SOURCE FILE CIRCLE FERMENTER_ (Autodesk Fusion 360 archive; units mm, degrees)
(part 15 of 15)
sketch "Schizzo13" plane through (0, 25.4136, 0) normal (0, 1, 0) x axis (-1, 0, 0)
  line L1 (6.7534, 68.1854) -> (79.5534, 68.1854)
  line L2 (0.7534, -16.6146) -> (0.7534, 62.1854)
  line L3 (79.5534, -22.6146) -> (6.7534, -22.6146)
  line L4 (85.5534, 62.1854) -> (85.5534, -16.6146)
  line L5 (71.1534, 65.7854) -> (15.1534, 65.7854)
  line L6 (83.1534, -8.2146) -> (83.1534, 53.7854)
  line L7 (15.1534, -20.2146) -> (71.1534, -20.2146)
  line L8 (3.1534, 53.7854) -> (3.1534, -8.2146)
  line L9 (85.5534, 62.1854) -> (85.5534, -16.6146)
  line L10 (79.5534, -22.6146) -> (6.7534, -22.6146)
  line L11 (0.7534, -16.6146) -> (0.7534, 62.1854)
  line L12 (6.7534, 68.1854) -> (79.5534, 68.1854)
  arc A1 centre (6.7534, 62.1854) radius 6 clockwise from (0.7534, 62.1854) to (6.7534, 68.1854)
  arc A2 centre (6.7534, -16.6146) radius 6 clockwise from (6.7534, -22.6146) to (0.7534, -16.6146)
  arc A3 centre (79.5534, -16.6146) radius 6 clockwise from (85.5534, -16.6146) to (79.5534, -22.6146)
  arc A4 centre (79.5534, 62.1854) radius 6 clockwise from (79.5534, 68.1854) to (85.5534, 62.1854)
  circle C1 centre (7.1534, -16.2146) radius 1.725
  circle C2 centre (79.1534, -16.2146) radius 1.725
  circle C3 centre (79.1534, 61.7854) radius 1.875
  circle C4 centre (7.1534, 61.7854) radius 1.875
  arc A5 centre (71.1534, 61.7854) radius 4 clockwise from (71.1534, 65.7854) to (75.1534, 61.7854)
  arc A6 centre (79.1534, 61.7854) radius 4 clockwise from (79.1534, 57.7854) to (75.1534, 61.7854)
  arc A7 centre (79.1534, 53.7854) radius 4 clockwise from (79.1534, 57.7854) to (83.1534, 53.7854)
  arc A8 centre (79.1534, -8.2146) radius 4 clockwise from (83.1534, -8.2146) to (79.1534, -12.2146)
  arc A9 centre (79.1534, -16.2146) radius 4 clockwise from (75.1534, -16.2146) to (79.1534, -12.2146)
  arc A10 centre (71.1534, -16.2146) radius 4 clockwise from (75.1534, -16.2146) to (71.1534, -20.2146)
  arc A11 centre (15.1534, -16.2146) radius 4 clockwise from (15.1534, -20.2146) to (11.1534, -16.2146)
  arc A12 centre (7.1534, -16.2146) radius 4 clockwise from (7.1534, -12.2146) to (11.1534, -16.2146)
  arc A13 centre (7.1534, -8.2146) radius 4 clockwise from (7.1534, -12.2146) to (3.1534, -8.2146)
  arc A14 centre (7.1534, 53.7854) radius 4 clockwise from (3.1534, 53.7854) to (7.1534, 57.7854)
  arc A15 centre (7.1534, 61.7854) radius 4 clockwise from (11.1534, 61.7854) to (7.1534, 57.7854)
  arc A16 centre (15.1534, 61.7854) radius 4 clockwise from (11.1534, 61.7854) to (15.1534, 65.7854)
  arc A17 centre (79.5534, -16.6146) radius 6 clockwise from (85.5534, -16.6146) to (79.5534, -22.6146)
  arc A18 centre (6.7534, -16.6146) radius 6 clockwise from (6.7534, -22.6146) to (0.7534, -16.6146)
  arc A19 centre (6.7534, 62.1854) radius 6 clockwise from (0.7534, 62.1854) to (6.7534, 68.1854)
  arc A20 centre (79.5534, 62.1854) radius 6 clockwise from (79.5534, 68.1854) to (85.5534, 62.1854)
extrude "Estrusione14" add sketch "Schizzo13" along normal blind 2
sketch "Schizzo14" plane through (-3.1534, 0, 0) normal (-1, 0, 0) x axis (0, -1, 0)
  line L1 (-5.4136, -8.2146) -> (-25.4136, -8.2146)
  line L2 (-5.4136, 53.7854) -> (-5.4136, -8.2146)
  line L3 (-25.4136, 53.7854) -> (-5.4136, 53.7854)
  line L4 (-25.4136, -8.2146) -> (-25.4136, 53.7854)
  line L5 (-5.4136, -20.2146) -> (-25.4136, -20.2146)
  line L6 (-25.4136, -20.2146) -> (-5.4136, -20.2146)
  curve K1 (-17.4136, -20.2146) -> (-5.4136, -20.2146)
  curve K2 (-25.4136, 3.7854) -> (-17.4136, -20.2146)
  curve K3 (-25.4136, 27.7854) -> (-25.4136, 3.7854)
  curve K4 (-25.4136, 27.7854) -> (-5.4136, -20.2146)
  line L7 (-25.4136, -20.2146) -> (-5.4136, -20.2146)
  line L8 (-25.4136, -19.2578) -> (-25.4136, -20.2146)
  line L9 (-25.4136, 27.7854) -> (-25.4136, -19.2578)
  point P8 (-17.4136, -20.2146)
  point P9 (-25.4136, 3.7854)
  point P10 (-25.4136, 27.7854)
  point P7 (-5.4136, -20.2146)
  point P11 (-5.4136, -20.2146)
  point P6 (-25.4136, -20.2146)
  point P12 (-25.4136, -20.2146)
  coincident L6 P8
  coincident L4 P9
  coincident L4 P10
  coincident P7 P11
  coincident P6 P12
  perpendicular L6 L8
  parallel L4 L9
  dimension "d87" distance L6 P10 = 48
  dimension "d88" distance L6 P9 = 24
  dimension "d89" distance P7 P8 = 12
extrude "Estrusione15" add sketch "Schizzo14" profile of L1 L4 L5 L6 K4 L7 L8 L9 to an object
sketch "Schizzo15" plane through (0, 5.4136, 0) normal (0, -1, 0) x axis (1, 0, 0)
  line L1 (-6.7534, -22.6146) -> (-79.5534, -22.6146)
  line L2 (-0.7534, 62.1854) -> (-0.7534, -16.6146)
  line L3 (-35.6534, 68.1854) -> (-6.7534, 68.1854)
  line L4 (-35.6534, 65.7854) -> (-35.6534, 68.1854)
  line L5 (-15.1534, 65.7854) -> (-35.6534, 65.7854)
  line L6 (-3.1534, -8.2146) -> (-3.1534, 53.7854)
  line L7 (-71.1534, -20.2146) -> (-15.1534, -20.2146)
  line L8 (-83.1534, 53.7854) -> (-83.1534, -8.2146)
  line L9 (-50.6534, 65.7854) -> (-71.1534, 65.7854)
  line L10 (-50.6534, 68.1854) -> (-50.6534, 65.7854)
  line L11 (-79.5534, 68.1854) -> (-50.6534, 68.1854)
  line L12 (-85.5534, -16.6146) -> (-85.5534, 62.1854)
  circle C1 centre (-7.1534, -16.2146) radius 1.725
  circle C2 centre (-79.1534, -16.2146) radius 1.725
  circle C3 centre (-79.1534, 61.7854) radius 1.875
  circle C4 centre (-7.1534, 61.7854) radius 1.875
  arc A1 centre (-79.5534, -16.6146) radius 6 clockwise from (-79.5534, -22.6146) to (-85.5534, -16.6146)
  arc A2 centre (-6.7534, -16.6146) radius 6 clockwise from (-0.7534, -16.6146) to (-6.7534, -22.6146)
  arc A3 centre (-6.7534, 62.1854) radius 6 clockwise from (-6.7534, 68.1854) to (-0.7534, 62.1854)
  arc A4 centre (-15.1534, 61.7854) radius 4 clockwise from (-15.1534, 65.7854) to (-11.1534, 61.7854)
  arc A5 centre (-7.1534, 61.7854) radius 4 clockwise from (-7.1534, 57.7854) to (-11.1534, 61.7854)
  arc A6 centre (-7.1534, 53.7854) radius 4 clockwise from (-7.1534, 57.7854) to (-3.1534, 53.7854)
  arc A7 centre (-7.1534, -8.2146) radius 4 clockwise from (-3.1534, -8.2146) to (-7.1534, -12.2146)
  arc A8 centre (-7.1534, -16.2146) radius 4 clockwise from (-11.1534, -16.2146) to (-7.1534, -12.2146)
  arc A9 centre (-15.1534, -16.2146) radius 4 clockwise from (-11.1534, -16.2146) to (-15.1534, -20.2146)
  arc A10 centre (-71.1534, -16.2146) radius 4 clockwise from (-71.1534, -20.2146) to (-75.1534, -16.2146)
  arc A11 centre (-79.1534, -16.2146) radius 4 clockwise from (-79.1534, -12.2146) to (-75.1534, -16.2146)
  arc A12 centre (-79.1534, -8.2146) radius 4 clockwise from (-79.1534, -12.2146) to (-83.1534, -8.2146)
  arc A13 centre (-79.1534, 53.7854) radius 4 clockwise from (-83.1534, 53.7854) to (-79.1534, 57.7854)
  arc A14 centre (-79.1534, 61.7854) radius 4 clockwise from (-75.1534, 61.7854) to (-79.1534, 57.7854)
  arc A15 centre (-71.1534, 61.7854) radius 4 clockwise from (-75.1534, 61.7854) to (-71.1534, 65.7854)
  arc A16 centre (-79.5534, 62.1854) radius 6 clockwise from (-85.5534, 62.1854) to (-79.5534, 68.1854)
  circle C5 centre (-7.1534, -16.2146) radius 1.725
  circle C6 centre (-79.1534, -16.2146) radius 1.725
extrude "Estrusione16" cut sketch "Schizzo15" profile of C1 C2 C5 C6 against normal blind 20
fillet "Raccordo4" radius 20
fillet "Raccordo5" radius 1
sketch "Schizzo16" plane through (0, 0, 68.1854) normal (0, 0, 1) x axis (-1, 0, 0)
  line L1 (6.7534, -5.4136) -> (35.6534, -5.4136)
  line L2 (6.7534, -27.4136) -> (6.7534, -5.4136)
  line L3 (79.5534, -27.4136) -> (6.7534, -27.4136)
  line L4 (79.5534, -5.4136) -> (79.5534, -27.4136)
  line L5 (50.6534, -5.4136) -> (79.5534, -5.4136)
  line L6 (50.6534, -6.4136) -> (50.6534, -5.4136)
  line L7 (36.6534, -7.4136) -> (49.6534, -7.4136)
  line L8 (35.6534, -5.4136) -> (35.6534, -6.4136)
  arc A1 centre (49.6534, -6.4136) radius 1 clockwise from (50.6534, -6.4136) to (49.6534, -7.4136)
  arc A2 centre (36.6534, -6.4136) radius 1 clockwise from (36.6534, -7.4136) to (35.6534, -6.4136)
  circle C1 centre (43.1534, -7.4136) radius 1
  point P14 (43.1534, -7.4136)
  midpoint L7 P14
  dimension "d98" diameter C1 = 2
extrude "Estrusione17" cut sketch "Schizzo16" profile of L7 C1 against normal blind 15.378
sketch "Schizzo18" plane through (0, 0, -22.6146) normal (0, 0, -1) x axis (1, 0, 0)
  line L1 (-79.5534, -5.4136) -> (-6.7534, -5.4136)
  line L2 (-79.5534, -27.4136) -> (-79.5534, -5.4136)
  line L3 (-6.7534, -27.4136) -> (-79.5534, -27.4136)
  line L4 (-6.7534, -5.4136) -> (-6.7534, -27.4136)
  line L5 (-43.1534, -27.4136) -> (-43.1534, -5.4136)
  line L6 (-40.1534, -7.4136) -> (-46.1534, -7.4136)
  line L7 (-46.1534, -3.4136) -> (-40.1534, -3.4136)
  line L8 (-40.1534, -5.4136) -> (-46.1534, -5.4136)
  arc A1 centre (-40.1534, -5.4136) radius 2 clockwise from (-40.1534, -3.4136) to (-40.1534, -7.4136)
  arc A2 centre (-46.1534, -5.4136) radius 2 clockwise from (-46.1534, -7.4136) to (-46.1534, -3.4136)
  point P6 (-43.1534, -5.4136)
  point P7 (-43.1534, -27.4136)
  point P14 (-43.1534, -5.4136)
  point P13 (-40.1534, -5.4136)
  midpoint L1 P6
  midpoint L3 P7
  tangent L6 A1
  tangent A1 L7
  parallel L6 L7
  tangent L7 A2
  tangent L6 A2
  perpendicular L5 L8
  coincident P6 P14
  midpoint L8 P14
  dimension "d101" diameter A1 = 4
  dimension "d104" distance P13 P14 = 3
extrude "Estrusione18" cut sketch "Schizzo18" profile of L1 L6 A1 L7 A2 against normal blind 17.359
sketch "Schizzo19" plane through (0, 5.4136, 0) normal (0, 1, 0) x axis (-1, 0, 0)
  line L1 (48.1534, -22.6146) -> (48.1534, -20.2146)
  line L2 (79.5534, -22.6146) -> (48.1534, -22.6146)
  line L3 (85.5534, 62.1854) -> (85.5534, -16.6146)
  line L4 (50.6534, 68.1854) -> (79.5534, 68.1854)
  line L5 (50.6534, 65.7854) -> (50.6534, 68.1854)
  line L6 (71.1534, 65.7854) -> (50.6534, 65.7854)
  line L7 (83.1534, -16.2146) -> (83.1534, 53.7854)
  line L8 (48.1534, -20.2146) -> (79.1534, -20.2146)
  line L9 (38.1534, -20.2146) -> (38.1534, -22.6146)
  line L10 (7.1534, -20.2146) -> (38.1534, -20.2146)
  line L11 (3.1534, 53.7854) -> (3.1534, -16.2146)
  line L12 (35.6534, 65.7854) -> (15.1534, 65.7854)
  line L13 (35.6534, 68.1854) -> (35.6534, 65.7854)
  line L14 (6.7534, 68.1854) -> (35.6534, 68.1854)
  line L15 (0.7534, -16.6146) -> (0.7534, 62.1854)
  line L16 (38.1534, -22.6146) -> (6.7534, -22.6146)
  line L17 (79.5534, -21.4146) -> (48.1534, -21.4146)
  line L18 (84.3534, 62.1854) -> (84.3534, -16.6146)
  line L19 (50.6534, 66.9854) -> (79.5534, 66.9854)
  line L20 (6.7534, 66.9854) -> (35.6534, 66.9854)
  line L21 (1.9534, -16.6146) -> (1.9534, 62.1854)
  line L22 (38.1534, -21.4146) -> (6.7534, -21.4146)
  arc A1 centre (79.5534, -16.6146) radius 6 clockwise from (85.5534, -16.6146) to (79.5534, -22.6146)
  arc A2 centre (79.5534, 62.1854) radius 6 clockwise from (79.5534, 68.1854) to (85.5534, 62.1854)
  arc A3 centre (71.1534, 61.7854) radius 4 clockwise from (71.1534, 65.7854) to (75.1534, 61.7854)
  arc A4 centre (79.1534, 61.7854) radius 4 clockwise from (79.1534, 57.7854) to (75.1534, 61.7854)
  arc A5 centre (79.1534, 53.7854) radius 4 clockwise from (79.1534, 57.7854) to (83.1534, 53.7854)
  arc A6 centre (79.1534, -16.2146) radius 4 clockwise from (83.1534, -16.2146) to (79.1534, -20.2146)
  circle C1 centre (79.1534, 61.7854) radius 1.875
  arc A7 centre (7.1534, -16.2146) radius 4 clockwise from (7.1534, -20.2146) to (3.1534, -16.2146)
  arc A8 centre (7.1534, 53.7854) radius 4 clockwise from (3.1534, 53.7854) to (7.1534, 57.7854)
  arc A9 centre (7.1534, 61.7854) radius 4 clockwise from (11.1534, 61.7854) to (7.1534, 57.7854)
  arc A10 centre (15.1534, 61.7854) radius 4 clockwise from (11.1534, 61.7854) to (15.1534, 65.7854)
  arc A11 centre (6.7534, 62.1854) radius 6 clockwise from (0.7534, 62.1854) to (6.7534, 68.1854)
  arc A12 centre (6.7534, -16.6146) radius 6 clockwise from (6.7534, -22.6146) to (0.7534, -16.6146)
  circle C2 centre (7.1534, 61.7854) radius 1.875
  arc A13 centre (79.5534, -16.6146) radius 4.8 clockwise from (84.3534, -16.6146) to (79.5534, -21.4146)
  arc A14 centre (79.5534, 62.1854) radius 4.8 clockwise from (79.5534, 66.9854) to (84.3534, 62.1854)
  arc A15 centre (6.7534, 62.1854) radius 4.8 clockwise from (1.9534, 62.1854) to (6.7534, 66.9854)
  arc A16 centre (6.7534, -16.6146) radius 4.8 clockwise from (6.7534, -21.4146) to (1.9534, -16.6146)
  dimension "d105" = -1.2
  dimension "d106" = -1.2
extrude "Estrusione19" cut sketch "Schizzo19" profile of L1 L2 A1 L3 A2 L4 L5 L9 L13 L14 A11 L15 A12 L16 A13 L17 L18 A14 L19 L20 L21 A15 A16 L22 against normal blind 1
extrude "Estrusione20" cut of existing geometry blind -13.899
sketch "Schizzo20" plane through (0, 5.4136, 0) normal (0, -1, 0) x axis (1, 0, 0)
  line L1 (-48.1534, -20.2146) -> (-48.1534, -22.6146)
  line L2 (-71.1534, -20.2146) -> (-48.1534, -20.2146)
  line L3 (-83.1534, 53.7854) -> (-83.1534, -8.2146)
  line L4 (-50.6534, 65.7854) -> (-71.1534, 65.7854)
  line L5 (-50.6534, 68.1854) -> (-50.6534, 65.7854)
  line L6 (-79.5534, 68.1854) -> (-50.6534, 68.1854)
  line L7 (-85.5534, -16.6146) -> (-85.5534, 62.1854)
  line L8 (-48.1534, -22.6146) -> (-79.5534, -22.6146)
  line L9 (-38.1534, -22.6146) -> (-38.1534, -20.2146)
  line L10 (-6.7534, -22.6146) -> (-38.1534, -22.6146)
  line L11 (-0.7534, 62.1854) -> (-0.7534, -16.6146)
  line L12 (-35.6534, 68.1854) -> (-6.7534, 68.1854)
  line L13 (-35.6534, 65.7854) -> (-35.6534, 68.1854)
  line L14 (-15.1534, 65.7854) -> (-35.6534, 65.7854)
  line L15 (-3.1534, -8.2146) -> (-3.1534, 53.7854)
  line L16 (-38.1534, -20.2146) -> (-15.1534, -20.2146)
  line L17 (-79.5534, 67.3854) -> (-50.6534, 67.3854)
  line L18 (-84.7534, -16.6146) -> (-84.7534, 62.1854)
  line L19 (-48.1534, -21.8146) -> (-79.5534, -21.8146)
  line L20 (-6.7534, -21.8146) -> (-38.1534, -21.8146)
  line L21 (-1.5534, 62.1854) -> (-1.5534, -16.6146)
  line L22 (-35.6534, 67.3854) -> (-6.7534, 67.3854)
  arc A1 centre (-71.1534, -16.2146) radius 4 clockwise from (-71.1534, -20.2146) to (-75.1534, -16.2146)
  arc A2 centre (-79.1534, -16.2146) radius 4 clockwise from (-79.1534, -12.2146) to (-75.1534, -16.2146)
  arc A3 centre (-79.1534, -8.2146) radius 4 clockwise from (-79.1534, -12.2146) to (-83.1534, -8.2146)
  arc A4 centre (-79.1534, 53.7854) radius 4 clockwise from (-83.1534, 53.7854) to (-79.1534, 57.7854)
  arc A5 centre (-79.1534, 61.7854) radius 4 clockwise from (-75.1534, 61.7854) to (-79.1534, 57.7854)
  arc A6 centre (-71.1534, 61.7854) radius 4 clockwise from (-75.1534, 61.7854) to (-71.1534, 65.7854)
  arc A7 centre (-79.5534, 62.1854) radius 6 clockwise from (-85.5534, 62.1854) to (-79.5534, 68.1854)
  arc A8 centre (-79.5534, -16.6146) radius 6 clockwise from (-79.5534, -22.6146) to (-85.5534, -16.6146)
  circle C1 centre (-79.1534, -16.2146) radius 1.725
  circle C2 centre (-79.1534, 61.7854) radius 1.875
  circle C3 centre (-7.1534, -16.2146) radius 1.725
  circle C4 centre (-7.1534, 61.7854) radius 1.875
  arc A9 centre (-6.7534, -16.6146) radius 6 clockwise from (-0.7534, -16.6146) to (-6.7534, -22.6146)
  arc A10 centre (-6.7534, 62.1854) radius 6 clockwise from (-6.7534, 68.1854) to (-0.7534, 62.1854)
  arc A11 centre (-15.1534, 61.7854) radius 4 clockwise from (-15.1534, 65.7854) to (-11.1534, 61.7854)
  arc A12 centre (-7.1534, 61.7854) radius 4 clockwise from (-7.1534, 57.7854) to (-11.1534, 61.7854)
  arc A13 centre (-7.1534, 53.7854) radius 4 clockwise from (-7.1534, 57.7854) to (-3.1534, 53.7854)
  arc A14 centre (-7.1534, -8.2146) radius 4 clockwise from (-3.1534, -8.2146) to (-7.1534, -12.2146)
  arc A15 centre (-7.1534, -16.2146) radius 4 clockwise from (-11.1534, -16.2146) to (-7.1534, -12.2146)
  arc A16 centre (-15.1534, -16.2146) radius 4 clockwise from (-11.1534, -16.2146) to (-15.1534, -20.2146)
  arc A17 centre (-79.5534, 62.1854) radius 5.2 clockwise from (-84.7534, 62.1854) to (-79.5534, 67.3854)
  arc A18 centre (-79.5534, -16.6146) radius 5.2 clockwise from (-79.5534, -21.8146) to (-84.7534, -16.6146)
  arc A19 centre (-6.7534, -16.6146) radius 5.2 clockwise from (-1.5534, -16.6146) to (-6.7534, -21.8146)
  arc A20 centre (-6.7534, 62.1854) radius 5.2 clockwise from (-6.7534, 67.3854) to (-1.5534, 62.1854)
  dimension "d111" = -0.8
  dimension "d112" = -0.8
extrude "Estrusione21" add sketch "Schizzo20" profile of L1 L5 L6 A7 L7 A8 L8 L9 L10 A9 L11 A10 L12 L13 L19 L17 A17 L18 A18 L20 A19 L21 A20 L22 along normal blind 0.8
thread "Filettatura"
sketch "Schizzo21" plane through (0, 5.4136, 0) normal (0, -1, 0) x axis (1, 0, 0)
  curve K1 (-6.1953, 60.9602) -> (-6.7549, 63.2761)
  curve K2 (-7.5519, 63.2761) -> (-8.1115, 60.9602)
  curve K3 (-8.1115, -15.3893) -> (-7.5519, -17.7052)
  curve K4 (-6.7549, -17.7052) -> (-6.1953, -15.3893)
  line L1 (-35.6534, 67.3854) -> (-6.7534, 67.3854)
  line L2 (-35.6534, 65.7854) -> (-35.6534, 67.3854)
  line L3 (-15.1534, 65.7854) -> (-35.6534, 65.7854)
  line L4 (-3.1534, -8.2146) -> (-3.1534, 53.7854)
  line L5 (-38.1534, -20.2146) -> (-15.1534, -20.2146)
  line L6 (-38.1534, -21.8146) -> (-38.1534, -20.2146)
  line L7 (-6.7534, -21.8146) -> (-38.1534, -21.8146)
  line L8 (-1.5534, 62.1854) -> (-1.5534, -16.6146)
  curve K5 (-78.1953, 60.9602) -> (-78.7549, 63.2761)
  curve K6 (-79.5519, 63.2761) -> (-80.1115, 60.9602)
  curve K7 (-80.1115, -15.3893) -> (-79.5519, -17.7052)
  curve K8 (-78.7549, -17.7052) -> (-78.1953, -15.3893)
  line L9 (-48.1534, -21.8146) -> (-79.5534, -21.8146)
  line L10 (-48.1534, -20.2146) -> (-48.1534, -21.8146)
  line L11 (-71.1534, -20.2146) -> (-48.1534, -20.2146)
  line L12 (-83.1534, 53.7854) -> (-83.1534, -8.2146)
  line L13 (-50.6534, 65.7854) -> (-71.1534, 65.7854)
  line L14 (-50.6534, 67.3854) -> (-50.6534, 65.7854)
  line L15 (-79.5534, 67.3854) -> (-50.6534, 67.3854)
  line L16 (-84.7534, -16.6146) -> (-84.7534, 62.1854)
  line L17 (-36.6534, 72.7854) -> (-36.6534, 62.7854)
  line L18 (-49.6534, 72.7854) -> (-36.6534, 72.7854)
  line L19 (-49.6534, 62.7854) -> (-49.6534, 72.7854)
  line L20 (-36.6534, 62.7854) -> (-49.6534, 62.7854)
  line L21 (-43.1534, 62.7854) -> (-43.1534, 72.7854)
  line L22 (-35.6534, 72.7854) -> (-36.6534, 72.7854)
  line L23 (-36.6534, 62.7854) -> (-36.6534, 72.7854)
  line L24 (-36.6534, 62.7854) -> (-35.6534, 62.7854)
  line L25 (-35.6534, 72.7854) -> (-35.6534, 62.7854)
  line L26 (-35.6534, 64.2854) -> (-30.6534, 65.7854)
  line L27 (-50.6534, 64.2854) -> (-55.6534, 65.7854)
  line L28 (-50.6534, 65.7854) -> (-50.6534, 64.2854)
  arc A1 centre (-7.1534, 61.7854) radius 1.2645 clockwise from (-6.1953, 60.9602) to (-8.1115, 60.9602)
  arc A2 centre (-7.1534, 61.7854) radius 1.543 clockwise from (-7.5519, 63.2761) to (-6.7549, 63.2761)
  arc A3 centre (-7.1534, -16.2146) radius 1.2645 clockwise from (-8.1115, -15.3893) to (-6.1953, -15.3893)
  arc A4 centre (-7.1534, -16.2146) radius 1.543 clockwise from (-6.7549, -17.7052) to (-7.5519, -17.7052)
  arc A5 centre (-15.1534, 61.7854) radius 4 clockwise from (-15.1534, 65.7854) to (-11.1534, 61.7854)
  arc A6 centre (-7.1534, 61.7854) radius 4 clockwise from (-7.1534, 57.7854) to (-11.1534, 61.7854)
  arc A7 centre (-7.1534, 53.7854) radius 4 clockwise from (-7.1534, 57.7854) to (-3.1534, 53.7854)
  arc A8 centre (-7.1534, -8.2146) radius 4 clockwise from (-3.1534, -8.2146) to (-7.1534, -12.2146)
  arc A9 centre (-7.1534, -16.2146) radius 4 clockwise from (-11.1534, -16.2146) to (-7.1534, -12.2146)
  arc A10 centre (-15.1534, -16.2146) radius 4 clockwise from (-11.1534, -16.2146) to (-15.1534, -20.2146)
  arc A11 centre (-6.7534, -16.6146) radius 5.2 clockwise from (-1.5534, -16.6146) to (-6.7534, -21.8146)
  arc A12 centre (-6.7534, 62.1854) radius 5.2 clockwise from (-6.7534, 67.3854) to (-1.5534, 62.1854)
  arc A13 centre (-79.1534, 61.7854) radius 1.2645 clockwise from (-78.1953, 60.9602) to (-80.1115, 60.9602)
  arc A14 centre (-79.1534, 61.7854) radius 1.543 clockwise from (-79.5519, 63.2761) to (-78.7549, 63.2761)
  arc A15 centre (-79.1534, -16.2146) radius 1.2645 clockwise from (-80.1115, -15.3893) to (-78.1953, -15.3893)
  arc A16 centre (-79.1534, -16.2146) radius 1.543 clockwise from (-78.7549, -17.7052) to (-79.5519, -17.7052)
  arc A17 centre (-71.1534, -16.2146) radius 4 clockwise from (-71.1534, -20.2146) to (-75.1534, -16.2146)
  arc A18 centre (-79.1534, -16.2146) radius 4 clockwise from (-79.1534, -12.2146) to (-75.1534, -16.2146)
  arc A19 centre (-79.1534, -8.2146) radius 4 clockwise from (-79.1534, -12.2146) to (-83.1534, -8.2146)
  arc A20 centre (-79.1534, 53.7854) radius 4 clockwise from (-83.1534, 53.7854) to (-79.1534, 57.7854)
  arc A21 centre (-79.1534, 61.7854) radius 4 clockwise from (-75.1534, 61.7854) to (-79.1534, 57.7854)
  arc A22 centre (-71.1534, 61.7854) radius 4 clockwise from (-75.1534, 61.7854) to (-71.1534, 65.7854)
  arc A23 centre (-79.5534, 62.1854) radius 5.2 clockwise from (-84.7534, 62.1854) to (-79.5534, 67.3854)
  arc A24 centre (-79.5534, -16.6146) radius 5.2 clockwise from (-79.5534, -21.8146) to (-84.7534, -16.6146)
  point P70 (-43.1534, 72.7854)
  point P71 (-43.1534, 62.7854)
  point P76 (-30.6534, 65.7854)
  point P77 (-35.6534, 64.2854)
  point P78 (-55.6534, 65.7854)
  point P79 (-50.6534, 64.2854)
  point P59 (-50.6534, 65.7854)
  point P80 (-50.6534, 65.7854)
  point P14 (-35.6534, 65.7854)
  midpoint L18 P70
  midpoint L20 P71
  coincident L3 P76
  coincident L25 P77
  symmetric L21 P76 P78
  symmetric L21 P77 P79
  coincident P59 P80
  dimension "d115" distance P14 P77 = 1.5
  dimension "d116" distance P14 P76 = 5
extrude "Estrusione22" add sketch "Schizzo21" profile of L3 L13 L25 L26 L27 L28 against normal blind 13.536
extrude "Estrusione23" cut of existing geometry blind -18.757
extrude "Estrusione24" add sketch "Schizzo21" profile of L3 L13 L25 L26 L27 L28 along normal blind 11
fillet "Raccordo6" radius 0.5 5
fillet "Raccordo7" radius 5 0.5
component_from_bodies "Corpo->Comp2"
component_from_bodies "Corpo->Comp3"
joint "Assembla5" alignAngle 90 alignOffsetX 0 alignOffsetY 0 alignOffsetZ 0
joint "Assembla6" alignAngle 0 alignOffsetX 0 alignOffsetY 0.2 alignOffsetZ 0
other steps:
base_feature "Lavorazione di base1"
base_feature "Lavorazione di base1"
joint_origin "OrigineGiunto1"
create_component "CreaComponente2"
remove_body "RimuoviCorpo2"
create_component "CreaComponente3"
remove_body "RimuoviCorpo3"
joint_origin "OrigineGiunto1"
joint_origin "OrigineGiunto1"
joint_origin "OrigineGiunto2"

design "MAGNETE 10x3"
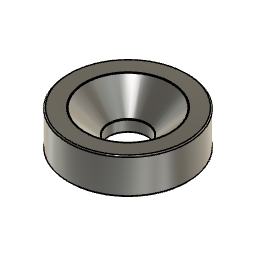
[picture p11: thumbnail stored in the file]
sketch "Schizzo" plane through (0, 0, 0) normal (0, 1, 0) x axis (1, 0, 0)
  line L1 (0, -69.005) -> (0, 0)
  line L2 (5, 0) -> (0, 0)
  line L3 (5, -3) -> (5, 0)
  line L4 (3.6, -3) -> (5, -3)
  line L5 (1.6, -1) -> (3.6, -3)
  line L6 (1.6, 0) -> (1.6, -1)
  point P1 (0, 0)
  point P2 (0, 0)
  point P4 (0, 0)
  point P9 (1.6, 0)
  point P5 (5, 0)
  point P6 (5, -3)
  point P7 (3.6, -3)
  point P8 (1.6, -1)
  coincident P1 P2
  vertical L1
  coincident P1 P4
  perpendicular L1 L2
  perpendicular L2 L3
  perpendicular L3 L4
  coincident L2 P9
  perpendicular L2 L6
  dimension "d1" distance P5 P6 = 3
  dimension "d2" = 10
  dimension "d3" = 3.2
  dimension "d4" angle L5 L6 = 135
  dimension "d5" distance P7 P8 = 2
revolve "Rivoluzione" sketch "Schizzo" AlongAngle 360
fillet "Raccordo" radius 0.1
